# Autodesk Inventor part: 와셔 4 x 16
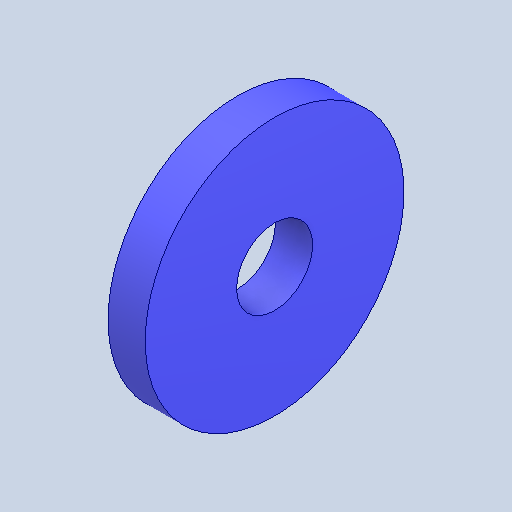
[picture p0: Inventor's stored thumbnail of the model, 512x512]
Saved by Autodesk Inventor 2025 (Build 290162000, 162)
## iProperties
Created: 2024-07
Part Number: 와셔 4 x 16
Material: 강철, 연강
Description: 미터법 평면 와셔
Document SubType Name: Modeling
Designer: 학생
Density: 7.85 g/cm^3
Appearance: 기본값
Author: jhkim
Sending System: Autodesk Inventor 2025
Preprocessor: ST-DEVELOPER v20
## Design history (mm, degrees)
feature "Solid1"
node "솔리드1"
